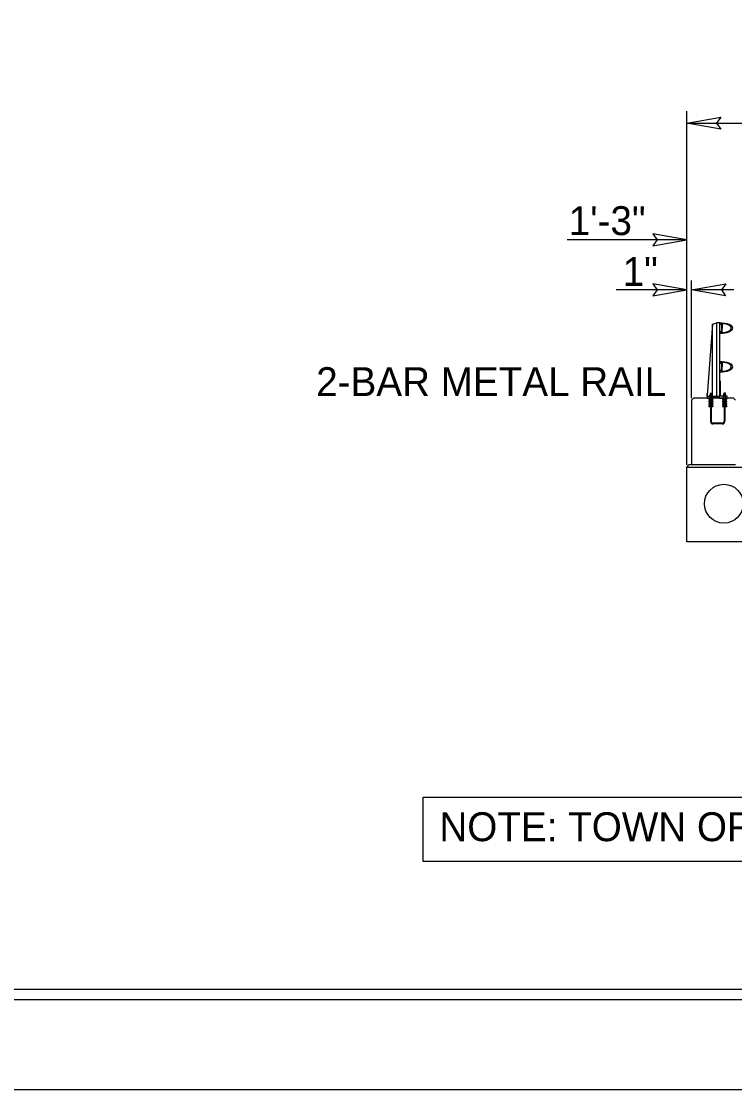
# Model space of a CAD drawing. Extents: x 693533 to 693723, y 486383 to 486493.
# Drawn here: x 693585.03 to 693602.77, y 486383.31 to 486409.89 of the extents above; entities that cross this region are included whole.
import ezdxf

# ---------------------------------------------------------------- set-up
doc = ezdxf.new("R2010")
doc.units = 0
for name, color, linetype in [('Old_Level_1', 7, 'Continuous'), ('Old_Level_28', 7, 'Continuous'), ('Sheet Cutting Line CELL', 7, 'Continuous'), ('Sheet Plot Border Inside CELL', 7, 'Continuous'), ('Sheet Plot Border Outside CELL', 7, 'Continuous'), ('Sheet Typical CELL', 7, 'Continuous'), ('Typical Bridge Rail Two Bar CELL', 7, 'Continuous')]:
    doc.layers.add(name, color=color, linetype=linetype)

msp = doc.modelspace()

# ---------------------------------------------------------------- linework, layer by layer
at = {"layer": 'Old_Level_1'}
msp.add_lwpolyline([(693595.018, 486390.588), (693644.204, 486390.588), (693644.204, 486388.993), (693595.018, 486388.993)], close=True, dxfattribs=at)
at = {"layer": 'Old_Level_28'}
for p, q in [((693601.581, 486398.856), (693601.581, 486407.663)), ((693601.581, 486407.359), (693634.581, 486407.359)), ((693601.581, 486404.458), (693598.599, 486404.458)), ((693601.697, 486400.52), (693601.697, 486403.447)), ((693601.581, 486403.211), (693599.818, 486403.211)), ((693602.75, 486403.211), (693601.697, 486403.211))]:
    msp.add_line(p, q, dxfattribs=at)
for points in [[(693602.424, 486407.213), (693601.581, 486407.359), (693602.429, 486407.509), (693602.321, 486407.359)], [(693600.737, 486404.313), (693601.581, 486404.458), (693600.732, 486404.608), (693600.84, 486404.458)], [(693600.737, 486403.066), (693601.581, 486403.211), (693600.732, 486403.361), (693600.84, 486403.211)], [(693602.541, 486403.066), (693601.697, 486403.211), (693602.546, 486403.361), (693602.438, 486403.211)], [(693601.581, 486398.804), (693604.581, 486398.804), (693604.581, 486396.944), (693601.581, 486396.944)]]:
    msp.add_lwpolyline(points, close=True, dxfattribs=at)
msp.add_circle((693602.501, 486397.892), 0.483, dxfattribs=at)
at = {"layer": 'Sheet Cutting Line CELL'}
msp.add_line((693532.659, 486383.314), (693701.059, 486383.314), dxfattribs=at)
at = {"layer": 'Sheet Plot Border Inside CELL'}
msp.add_lwpolyline([(693700.609, 486491.069), (693533.959, 486491.069), (693533.959, 486385.559), (693700.609, 486385.559)], close=True, dxfattribs=at)
at = {"layer": 'Sheet Plot Border Outside CELL'}
msp.add_lwpolyline([(693701.059, 486493.314), (693532.659, 486493.314), (693532.659, 486383.314), (693701.059, 486383.314)], close=True, dxfattribs=at)
at = {"layer": 'Sheet Typical CELL'}
msp.add_lwpolyline([(693699.359, 486490.814), (693549.359, 486490.814), (693549.359, 486385.814), (693699.359, 486385.814)], close=True, dxfattribs=at)
at = {"layer": 'Typical Bridge Rail Two Bar CELL'}
for p, q in [((693602.214, 486402.356), (693602.086, 486400.593)), ((693602.214, 486402.356), (693602.325, 486402.392)), ((693602.214, 486400.557), (693602.214, 486402.356)), ((693602.399, 486402.392), (693602.325, 486402.392)), ((693602.325, 486400.557), (693602.325, 486402.392)), ((693602.399, 486400.557), (693602.399, 486402.392)), ((693602.46, 486402.362), (693602.46, 486402.262)), ((693602.46, 486402.162), (693602.46, 486402.262)), ((693602.214, 486401.514), (693602.21, 486401.514)), ((693602.46, 486401.4), (693602.46, 486401.3)), ((693602.46, 486401.2), (693602.46, 486401.3)), ((693601.697, 486400.472), (693601.745, 486400.52)), ((693601.697, 486400.472), (693601.697, 486398.856)), ((693602.74, 486400.52), (693601.745, 486400.52)), ((693602.086, 486400.557), (693602.086, 486400.593)), ((693602.089, 486400.614), (693602.089, 486400.646)), ((693602.226, 486400.485), (693602.128, 486400.485)), ((693602.226, 486400.474), (693602.128, 486400.474)), ((693602.169, 486400.441), (693602.128, 486400.441)), ((693602.169, 486400.43), (693602.128, 486400.43)), ((693602.169, 486400.463), (693602.15, 486400.463)), ((693602.169, 486400.452), (693602.15, 486400.452)), ((693602.169, 486400.419), (693602.15, 486400.419)), ((693602.169, 486400.409), (693602.15, 486400.409)), ((693602.157, 486400.475), (693602.157, 486400.557)), ((693602.199, 486400.631), (693602.158, 486400.631)), ((693602.158, 486400.631), (693602.158, 486400.596)), ((693602.185, 486400.463), (693602.169, 486400.463)), ((693602.169, 486400.463), (693602.169, 486399.946)), ((693602.204, 486400.463), (693602.185, 486400.463)), ((693602.185, 486400.463), (693602.185, 486399.946)), ((693602.204, 486400.452), (693602.185, 486400.452)), ((693602.226, 486400.441), (693602.185, 486400.441)), ((693602.226, 486400.43), (693602.185, 486400.43)), ((693602.204, 486400.419), (693602.185, 486400.419)), ((693602.204, 486400.409), (693602.185, 486400.409)), ((693602.199, 486400.596), (693602.199, 486400.631)), ((693602.199, 486400.475), (693602.199, 486400.557)), ((693602.565, 486400.485), (693602.468, 486400.485)), ((693602.565, 486400.474), (693602.468, 486400.474)), ((693602.509, 486400.441), (693602.468, 486400.441)), ((693602.509, 486400.43), (693602.468, 486400.43)), ((693602.509, 486400.463), (693602.49, 486400.463)), ((693602.509, 486400.452), (693602.49, 486400.452)), ((693602.509, 486400.419), (693602.49, 486400.419)), ((693602.509, 486400.409), (693602.49, 486400.409)), ((693602.495, 486400.485), (693602.495, 486400.566)), ((693602.539, 486400.64), (693602.497, 486400.64)), ((693602.497, 486400.64), (693602.497, 486400.606)), ((693602.525, 486400.463), (693602.509, 486400.463)), ((693602.509, 486400.463), (693602.509, 486399.946)), ((693602.544, 486400.463), (693602.525, 486400.463)), ((693602.525, 486400.463), (693602.525, 486399.946)), ((693602.544, 486400.452), (693602.525, 486400.452)), ((693602.565, 486400.441), (693602.525, 486400.441)), ((693602.565, 486400.43), (693602.525, 486400.43)), ((693602.544, 486400.419), (693602.525, 486400.419)), ((693602.544, 486400.409), (693602.525, 486400.409)), ((693602.539, 486400.606), (693602.539, 486400.64)), ((693602.541, 486400.485), (693602.541, 486400.566)), ((693602.74, 486400.52), (693602.787, 486400.472)), ((693602.169, 486400.398), (693602.128, 486400.398)), ((693602.169, 486400.387), (693602.128, 486400.387)), ((693602.169, 486400.355), (693602.128, 486400.355)), ((693602.169, 486400.344), (693602.128, 486400.344)), ((693602.169, 486400.311), (693602.128, 486400.311)), ((693602.169, 486400.301), (693602.128, 486400.301)), ((693602.169, 486400.376), (693602.15, 486400.376)), ((693602.169, 486400.365), (693602.15, 486400.365)), ((693602.169, 486400.333), (693602.15, 486400.333)), ((693602.169, 486400.322), (693602.15, 486400.322)), ((693602.226, 486400.398), (693602.185, 486400.398)), ((693602.226, 486400.387), (693602.185, 486400.387)), ((693602.204, 486400.376), (693602.185, 486400.376)), ((693602.204, 486400.365), (693602.185, 486400.365)), ((693602.226, 486400.355), (693602.185, 486400.355)), ((693602.226, 486400.344), (693602.185, 486400.344)), ((693602.204, 486400.333), (693602.185, 486400.333)), ((693602.204, 486400.322), (693602.185, 486400.322)), ((693602.226, 486400.311), (693602.185, 486400.311)), ((693602.226, 486400.301), (693602.185, 486400.301)), ((693602.509, 486400.398), (693602.468, 486400.398)), ((693602.509, 486400.387), (693602.468, 486400.387)), ((693602.509, 486400.355), (693602.468, 486400.355)), ((693602.509, 486400.344), (693602.468, 486400.344)), ((693602.509, 486400.311), (693602.468, 486400.311)), ((693602.509, 486400.301), (693602.468, 486400.301)), ((693602.509, 486400.376), (693602.49, 486400.376)), ((693602.509, 486400.365), (693602.49, 486400.365)), ((693602.509, 486400.333), (693602.49, 486400.333)), ((693602.509, 486400.322), (693602.49, 486400.322)), ((693602.565, 486400.398), (693602.525, 486400.398)), ((693602.565, 486400.387), (693602.525, 486400.387)), ((693602.544, 486400.376), (693602.525, 486400.376)), ((693602.544, 486400.365), (693602.525, 486400.365)), ((693602.565, 486400.355), (693602.525, 486400.355)), ((693602.565, 486400.344), (693602.525, 486400.344)), ((693602.544, 486400.333), (693602.525, 486400.333)), ((693602.544, 486400.322), (693602.525, 486400.322)), ((693602.565, 486400.311), (693602.525, 486400.311)), ((693602.565, 486400.301), (693602.525, 486400.301)), ((693602.457, 486399.894), (693602.237, 486399.894)), ((693602.457, 486399.878), (693602.237, 486399.878)), ((693601.581, 486398.804), (693601.628, 486398.856)), ((693601.707, 486398.856), (693601.628, 486398.856)), ((693602.787, 486398.856), (693601.707, 486398.856))]:
    msp.add_line(p, q, dxfattribs=at)
for points in [[(693602.399, 486402.135), (693602.399, 486402.182), (693602.418, 486402.182), (693602.418, 486402.175), (693602.416, 486402.175), (693602.416, 486402.155), (693602.448, 486402.155), (693602.452, 486402.185), (693602.452, 486402.262), (693602.452, 486402.339), (693602.448, 486402.369), (693602.416, 486402.369), (693602.416, 486402.349), (693602.418, 486402.349), (693602.418, 486402.341), (693602.399, 486402.341), (693602.399, 486402.389)], [(693602.399, 486401.173), (693602.399, 486401.221), (693602.418, 486401.221), (693602.418, 486401.213), (693602.416, 486401.213), (693602.416, 486401.193), (693602.448, 486401.193), (693602.452, 486401.223), (693602.452, 486401.3), (693602.452, 486401.377), (693602.448, 486401.407), (693602.416, 486401.407), (693602.416, 486401.388), (693602.418, 486401.388), (693602.418, 486401.38), (693602.399, 486401.38), (693602.399, 486401.427)], [(693602.587, 486400.52), (693602.587, 486400.566), (693602.417, 486400.566), (693602.417, 486400.942), (693602.399, 486400.942), (693602.399, 486400.557), (693602.095, 486400.557), (693602.095, 486400.584), (693602.086, 486400.584), (693602.086, 486400.52), (693602.232, 486400.52), (693602.232, 486400.545), (693602.38, 486400.545), (693602.38, 486400.52), (693602.587, 486400.52)], [(693602.128, 486400.485), (693602.128, 486400.474), (693602.15, 486400.463), (693602.15, 486400.452), (693602.128, 486400.441), (693602.128, 486400.43), (693602.15, 486400.419), (693602.15, 486400.409), (693602.128, 486400.398), (693602.128, 486400.387), (693602.15, 486400.376), (693602.15, 486400.365), (693602.128, 486400.355), (693602.128, 486400.344), (693602.15, 486400.333), (693602.15, 486400.322), (693602.128, 486400.311), (693602.128, 486400.301)], [(693602.22, 486400.556), (693602.22, 486400.564), (693602.178, 486400.564), (693602.136, 486400.564), (693602.136, 486400.556)], [(693602.209, 486400.564), (693602.209, 486400.591), (693602.204, 486400.596), (693602.153, 486400.596), (693602.147, 486400.591), (693602.147, 486400.564), (693602.209, 486400.564), (693602.189, 486400.564), (693602.189, 486400.591), (693602.194, 486400.596), (693602.189, 486400.591), (693602.184, 486400.596), (693602.173, 486400.596), (693602.168, 486400.591), (693602.168, 486400.564), (693602.168, 486400.591), (693602.163, 486400.596)], [(693602.226, 486400.485), (693602.226, 486400.474), (693602.205, 486400.463), (693602.205, 486400.452), (693602.226, 486400.441), (693602.226, 486400.43), (693602.205, 486400.419), (693602.205, 486400.409), (693602.226, 486400.398), (693602.226, 486400.387), (693602.205, 486400.376), (693602.205, 486400.365), (693602.226, 486400.355), (693602.226, 486400.344), (693602.205, 486400.333), (693602.205, 486400.322), (693602.226, 486400.311), (693602.226, 486400.301)], [(693602.468, 486400.485), (693602.468, 486400.474), (693602.49, 486400.463), (693602.49, 486400.452), (693602.468, 486400.441), (693602.468, 486400.43), (693602.49, 486400.419), (693602.49, 486400.409), (693602.468, 486400.398), (693602.468, 486400.387), (693602.49, 486400.376), (693602.49, 486400.365), (693602.468, 486400.355), (693602.468, 486400.344), (693602.49, 486400.333), (693602.49, 486400.322), (693602.468, 486400.311), (693602.468, 486400.301)], [(693602.561, 486400.566), (693602.561, 486400.574), (693602.519, 486400.574), (693602.477, 486400.574), (693602.477, 486400.566)], [(693602.549, 486400.574), (693602.549, 486400.6), (693602.544, 486400.605), (693602.492, 486400.605), (693602.487, 486400.6), (693602.487, 486400.574), (693602.549, 486400.574), (693602.528, 486400.574), (693602.528, 486400.6), (693602.534, 486400.605), (693602.528, 486400.6), (693602.523, 486400.605), (693602.513, 486400.605), (693602.508, 486400.6), (693602.508, 486400.574), (693602.508, 486400.6), (693602.503, 486400.605)], [(693602.566, 486400.485), (693602.566, 486400.474), (693602.544, 486400.463), (693602.544, 486400.452), (693602.566, 486400.441), (693602.566, 486400.43), (693602.544, 486400.419), (693602.544, 486400.409), (693602.566, 486400.398), (693602.566, 486400.387), (693602.544, 486400.376), (693602.544, 486400.365), (693602.566, 486400.355), (693602.566, 486400.344), (693602.544, 486400.333), (693602.544, 486400.322), (693602.566, 486400.311), (693602.566, 486400.301)]]:
    msp.add_lwpolyline(points, dxfattribs=at)
for centre in [(693602.137, 486400.327), (693602.557, 486400.327)]:
    msp.add_circle(centre, 0.00813, dxfattribs=at)
for centre, radius, start, end in [((693602.468, 486402.362), 0.00763, 90, 180), ((693602.468, 486402.162), 0.00763, 180, 270), ((693602.468, 486401.4), 0.00763, 90, 180), ((693602.468, 486401.2), 0.00763, 180, 270), ((693602.237, 486399.946), 0.0683, 180, 270), ((693602.237, 486399.946), 0.052, 180, 270), ((693602.457, 486399.946), 0.052, 270, 0), ((693602.457, 486399.946), 0.0683, 270, 0)]:
    msp.add_arc(centre, radius, start, end, dxfattribs=at)
for centre, major_axis, ratio, start_param, end_param in [((693602.398, 486402.262), (0.326, 0), 0.39036, 6.282787, 7.853967), ((693602.468, 486402.262), (0.217, 0), 0.495501, 6.282718, 7.853881), ((693602.398, 486402.262), (0.326, 0), 0.39036, 4.712404, 6.282787), ((693602.468, 486402.262), (0.217, 0), 0.495501, 4.712489, 6.282718), ((693602.398, 486401.3), (0.326, 0), 0.39036, 6.282787, 7.853967), ((693602.398, 486401.3), (0.326, 0), 0.39036, 4.712404, 6.282787), ((693602.468, 486401.3), (0.217, 0), 0.495501, 6.282718, 7.853881), ((693602.468, 486401.3), (0.217, 0), 0.495501, 4.712489, 6.282718)]:
    msp.add_ellipse(centre, major_axis=major_axis, ratio=ratio, start_param=start_param, end_param=end_param, dxfattribs=at)

# ---------------------------------------------------------------- texts
at = {"layer": 'Old_Level_28'}
for s, height, p in [('1\'-3"', 0.7188, (693598.641, 486404.576)), ('1"', 0.7188, (693599.983, 486403.311)), ('2-BAR METAL RAIL', 0.71875, (693592.36, 486400.57)), ('NOTE: TOWN OF KNIGHTDALE HAS SR 2507 (TURNIPSEED ROAD) DESIGNATED A LOCAL BIKE ROUTE.', 0.71875, (693595.424, 486389.496))]:
    msp.add_text(s, height=height, rotation=360, dxfattribs=at).set_placement(p)

doc.saveas('drawing.dxf')
